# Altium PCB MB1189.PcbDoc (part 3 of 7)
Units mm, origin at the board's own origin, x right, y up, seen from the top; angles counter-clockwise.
Board outline 60.03 x 127.03 mm, 6 copper layers (TOP, L2_GND, L3_VCC, L4_SIG, L5_GND, BOTTOM), stack 1.58 mm thick; 273 components, 264 nets, 1114 pads, 811 vias.
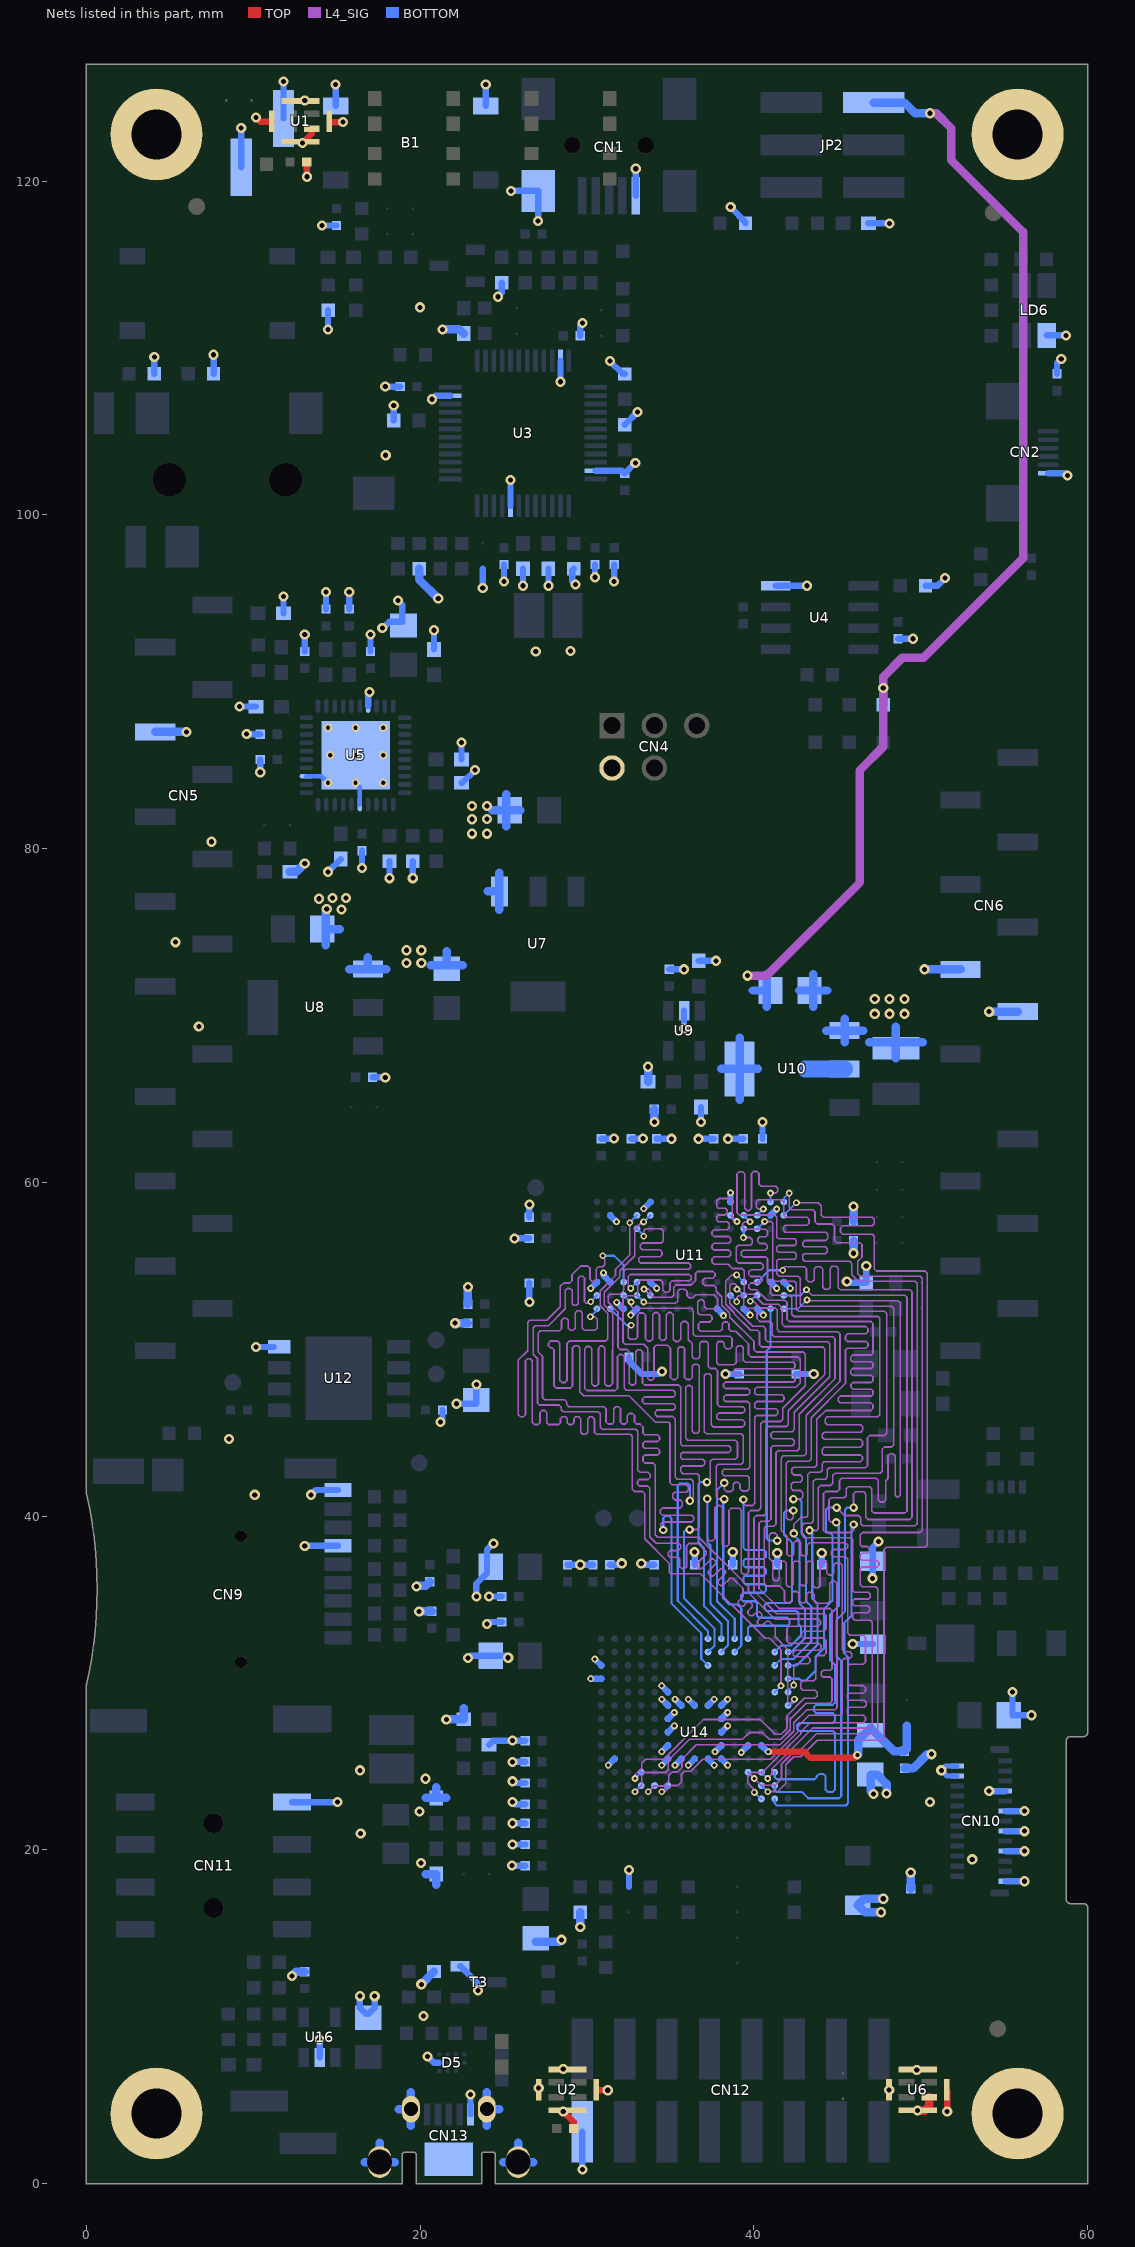
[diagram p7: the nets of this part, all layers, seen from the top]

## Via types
v1: diameter 0.61/0.61/0.61 (per signal layer), hole 0.305, TOP to BOTTOM, 321 vias
v2: diameter 0.508/0.508/0.508 (per signal layer), hole 0.254, TOP to BOTTOM, 247 vias
v3: diameter 0.406/0.406/0.406 (per signal layer), hole 0.203, TOP to BOTTOM, 243 vias

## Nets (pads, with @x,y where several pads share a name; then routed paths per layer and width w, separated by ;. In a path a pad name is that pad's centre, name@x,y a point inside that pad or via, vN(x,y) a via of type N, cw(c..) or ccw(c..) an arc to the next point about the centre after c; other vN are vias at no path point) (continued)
D5: U11.M8 U14.N9 | length 57
  L4_SIG w0.102: v3(32.561,57.578) 32.561,55.65 31.709,54.798 31.709,54.422 30.785,53.497 30.785,52.603 31.242,52.146 31.242,50.622 31.115,50.495 28.931,50.495 28.804,50.368 28.804,48.132 28.677,48.006 28.498,48.006 28.372,48.132 28.372,50.368 28.245,50.495 27.813,50.495 27.686,50.368 27.686,50.216 27.813,50.089 27.889,50.089 28.016,49.962 28.016,47.803 28.143,47.676 29.007,47.676 29.134,47.803 29.134,50.089 29.261,50.216 29.439,50.216 29.566,50.089 29.566,47.447 29.794,47.219 32.512,47.219 34.099,45.631 34.887,45.631 34.976,45.542 34.976,42.012 35.103,41.885 35.941,41.885 36.068,41.758 36.068,41.554 35.941,41.427 35.255,41.427 35.128,41.3 35.128,41.097 35.255,40.97 35.585,40.97 35.712,40.843 35.712,40.615 35.585,40.488 34.519,40.488 34.392,40.361 34.392,40.183 34.519,40.056 36.279,40.056 36.398,39.937 36.398,39.769 36.279,39.649 34.544,39.649 34.417,39.522 34.417,39.294 34.544,39.167 v2(34.569,39.167)
  BOTTOM w0.127: v3(32.561,57.578) 32.561,57.592 U11.M8@32.995,58.026 ; v2(34.569,39.167) 34.569,39.878 34.696,40.005 34.925,40.005 35.052,39.878 35.052,34.767 36.848,32.971 36.848,31.452 U14.N9@37.249,31.051
D6: U11.M7 U14.P9 | length 57.4
  L4_SIG w0.102: v3(33.401,56.769) 33.401,57.099 33.528,57.226 34.442,57.226 34.569,57.099 34.569,56.49 34.442,56.363 33.317,56.363 33.198,56.243 33.198,56.075 33.317,55.956 34.374,55.956 34.493,55.837 34.493,55.669 34.374,55.55 33.208,55.55 33.096,55.438 33.096,55.28 33.208,55.169 36.093,55.169 36.22,55.042 36.22,54.914 36.094,54.788 32.334,54.788 32.207,54.661 32.207,53.518 31.979,53.289 31.394,53.289 31.267,53.162 31.267,52.812 31.852,52.227 31.852,50.114 31.979,49.987 32.41,49.987 32.537,49.86 32.537,47.965 32.649,47.854 32.807,47.854 32.918,47.965 32.918,49.843 33.038,49.962 33.206,49.962 33.325,49.843 33.325,47.981 33.452,47.854 35.484,47.854 35.611,47.727 35.611,44.323 35.712,44.221 38.489,44.221 38.608,44.102 38.608,43.934 38.489,43.815 35.712,43.815 35.611,43.713 35.611,43.51 35.712,43.409 36.939,43.409 37.059,43.289 37.059,43.121 36.939,43.002 35.712,43.002 35.611,42.901 35.611,42.672 35.738,42.545 36.601,42.545 36.728,42.418 36.728,39.319 36.601,39.192 v2(36.144,39.192)
  BOTTOM w0.127: U11.M7@32.995,57.226 33.401,56.82 v3(33.401,56.769) ; v2(36.144,39.192) 35.941,39.192 35.814,39.065 35.814,35.083 37.647,33.25 37.647,32.249 U14.P9@37.249,31.851
D7: U11.L8 U14.R9 | length 56.9
  L4_SIG w0.102: v3(33.388,57.632) 33.299,57.632 32.855,57.188 32.855,55.613 31.953,54.712 31.953,54.331 31.039,53.416 31.039,52.654 31.547,52.146 31.547,49.987 31.521,49.962 31.521,47.93 31.394,47.803 31.191,47.803 31.064,47.93 31.064,50.063 30.937,50.19 30.81,50.19 30.683,50.063 30.683,47.922 30.564,47.803 30.396,47.803 30.277,47.922 30.277,50.046 30.158,50.165 29.99,50.165 29.87,50.046 29.87,47.65 29.997,47.523 31.699,47.523 31.826,47.65 31.826,49.563 31.945,49.682 32.113,49.682 32.233,49.563 32.233,47.676 32.36,47.549 35.161,47.549 35.281,47.43 35.281,47.262 35.161,47.142 33.444,47.142 33.325,47.023 33.325,46.855 33.444,46.736 35.169,46.736 35.281,46.624 35.281,46.467 35.169,46.355 34.198,46.355 34.087,46.243 34.087,46.086 34.198,45.974 35.128,45.974 35.281,45.822 35.281,42.342 35.408,42.215 36.246,42.215 36.373,42.088 36.373,41.046 36.246,40.919 v2(36.17,40.919)
  BOTTOM w0.127: v3(33.388,57.632) 33.401,57.645 33.414,57.645 U11.L8@33.795,58.026 ; v2(36.17,40.919) 36.17,41.834 36.043,41.961 35.56,41.961 35.433,41.834 35.433,34.925 37.249,33.109 U14.R9@37.249,32.651
D8: U11.L2 U14.P10 | length 56.8
  L4_SIG w0.102: v3(33.414,53.607) 33.692,53.607 33.807,53.492 33.807,53.238 33.934,53.111 35.077,53.111 35.204,53.238 35.204,53.721 35.331,53.848 36.246,53.848 36.5,54.102 36.5,54.559 36.601,54.661 37.549,54.661 37.668,54.542 37.668,54.374 37.549,54.254 37.059,54.254 36.932,54.127 36.932,53.95 37.059,53.823 37.617,53.823 37.744,53.696 37.744,53.467 38.075,53.137 38.075,52.629 38.557,52.146 38.557,51.918 40.005,50.47 40.005,49.962 40.132,49.835 42.951,49.835 43.078,49.708 43.078,47.803 41.732,46.457 41.732,45.796 41.605,45.669 40.538,45.669 40.411,45.542 40.411,40.462 40.284,40.335 39.802,40.335 39.675,40.208 39.675,36.626 39.548,36.5 39.369,36.5 39.243,36.626 39.243,40.335 39.116,40.462 38.633,40.462 38.506,40.335 38.506,38.321 38.387,38.202 38.219,38.202 38.1,38.321 38.1,40.514 37.974,40.64 37.795,40.64 37.668,40.514 37.668,38.659 37.541,38.532 37.338,38.532 37.211,38.659 v2(37.211,41.046)
  BOTTOM w0.127: v3(33.414,53.607) U11.L2@33.795,53.226 ; v2(37.211,41.046) 37.211,38.431 37.401,38.241 37.401,34.753 38.451,33.704 38.451,32.253 U14.P10@38.049,31.851
D9: U11.M3 U14.R10 | length 57.1
  L4_SIG w0.102: v3(32.618,53.649) 32.588,53.649 32.461,53.776 32.461,54.356 32.588,54.483 36.134,54.483 36.246,54.371 36.246,54.214 36.134,54.102 35.103,54.102 34.976,53.975 34.976,53.543 34.849,53.416 34.67,53.416 34.544,53.543 34.544,54.026 34.417,54.153 33.172,54.153 33.045,54.026 33.045,53.34 32.918,53.213 32.283,53.213 32.156,53.086 32.156,50.419 32.283,50.292 33.401,50.292 33.63,50.063 33.63,48.27 33.741,48.158 33.899,48.158 34.011,48.27 34.011,50.114 34.138,50.241 34.823,50.241 35.001,50.063 35.001,48.311 35.128,48.184 35.312,48.184 35.439,48.311 35.439,50.02 35.558,50.14 35.726,50.14 35.845,50.02 35.845,48.311 35.972,48.184 36.17,48.184 36.297,48.311 36.297,48.972 36.423,49.098 36.602,49.098 36.728,48.972 36.728,45.085 36.601,44.958 36.424,44.958 36.297,45.085 36.297,47.717 36.185,47.828 36.027,47.828 35.916,47.717 35.916,44.679 36.043,44.552 38.887,44.552 39.014,44.425 39.014,43.536 38.887,43.409 37.516,43.409 37.389,43.282 37.389,42.164 37.262,42.037 v2(37.186,42.037)
  BOTTOM w0.127: v3(32.618,53.649) U11.M3@32.995,54.026 ; v2(37.186,42.037) 36.813,42.037 36.686,41.91 36.686,38.417 37.02,38.083 37.02,34.595 38.049,33.567 U14.R10@38.049,32.651
D10: U11.M2 U14.R12 | length 57.9
  L4_SIG w0.102: v3(33.401,52.832) 33.477,52.756 35.306,52.756 35.433,52.883 35.433,53.467 35.56,53.594 35.865,53.594 35.992,53.467 35.992,53.213 36.119,53.086 36.347,53.086 36.525,53.264 37.592,53.264 37.821,53.035 37.821,52.553 37.694,52.426 37.16,52.426 37.033,52.553 37.033,52.84 36.914,52.959 36.746,52.959 36.627,52.84 36.627,52.197 36.754,52.07 37.364,52.07 37.49,51.944 37.49,51.765 37.364,51.638 36.805,51.638 36.678,51.511 36.678,51.206 36.805,51.079 37.973,51.079 38.1,51.206 38.1,51.511 38.227,51.638 38.379,51.638 38.506,51.511 38.506,51.206 38.633,51.079 38.913,51.079 39.675,50.317 39.675,49.682 39.827,49.53 42.647,49.53 42.774,49.403 42.774,47.981 42.52,47.727 40.183,47.727 40.056,47.6 40.056,47.371 40.157,47.269 41.689,47.269 41.808,47.15 41.808,46.982 41.689,46.863 40.157,46.863 40.056,46.761 40.056,46.533 40.157,46.431 41.326,46.431 41.427,46.33 41.427,46.126 41.326,46.025 40.157,46.025 40.056,45.923 40.056,40.767 39.929,40.64 39.497,40.64 39.37,40.767 v2(39.37,40.996)
  BOTTOM w0.127: U11.M2@32.995,53.226 33.389,52.832 v3(33.401,52.832) ; v2(39.37,40.996) 39.37,38.1 39.497,37.973 40.589,37.973 40.716,37.846 40.716,37.567 40.589,37.44 39.497,37.44 39.37,37.313 39.37,37.059 39.497,36.932 40.589,36.932 40.716,36.805 40.716,36.551 40.589,36.424 39.497,36.424 39.37,36.297 39.37,36.043 39.497,35.916 40.589,35.916 40.716,35.789 40.716,35.535 40.589,35.408 39.37,35.408 39.243,35.281 39.243,35.027 39.37,34.9 40.056,34.9 40.183,34.773 40.183,34.036 40.31,33.909 42.012,33.909 42.139,33.782 42.139,33.553 42.012,33.426 39.776,33.426 39.649,33.299 U14.R12@39.649,32.651
D11: U11.P1 U14.P11 | length 57.3
  L4_SIG w0.102: v3(32.639,51.435) 32.588,51.435 32.461,51.308 32.461,50.724 32.588,50.597 32.893,50.597 33.02,50.724 33.02,52.045 33.147,52.172 33.376,52.172 33.503,52.045 33.503,50.622 33.63,50.495 33.811,50.495 33.938,50.622 33.938,52.07 34.065,52.197 34.218,52.197 34.345,52.07 34.345,50.665 34.464,50.546 34.632,50.546 34.751,50.665 34.751,52.07 34.878,52.197 35.03,52.197 35.157,52.07 35.157,50.597 35.284,50.47 35.484,50.47 35.611,50.597 35.611,51.537 35.738,51.664 35.941,51.664 36.068,51.537 36.068,50.571 36.297,50.343 36.297,49.555 36.424,49.428 36.627,49.428 36.754,49.555 36.754,50.343 36.881,50.47 37.135,50.47 37.262,50.343 37.262,48.971 37.389,48.844 37.694,48.844 37.821,48.717 37.821,46.685 37.948,46.558 39.335,46.558 39.446,46.447 39.446,46.289 39.335,46.177 37.889,46.177 37.77,46.058 37.77,45.89 37.889,45.771 39.32,45.771 39.446,45.644 39.446,45.465 39.32,45.339 37.567,45.339 37.44,45.466 37.44,48.42 37.32,48.539 37.152,48.539 37.033,48.42 37.033,45.06 37.16,44.933 39.243,44.933 39.37,44.806 39.37,43.231 39.243,43.104 37.871,43.104 37.744,42.977 37.744,41.148 37.871,41.021 v2(38.227,41.021)
  BOTTOM w0.127: U11.P1@31.395,52.426 32.386,51.435 v3(32.639,51.435) ; v2(38.227,41.021) 38.163,40.957 38.163,35.069 38.536,34.696 39.014,34.696 39.243,34.468 39.243,32.245 39.146,32.148 U14.P11@38.849,31.851
D12: U11.N2 U14.R11 | length 56.8
  L4_SIG w0.102: v3(32.639,52.832) 32.639,52.578 32.766,52.451 36.246,52.451 36.373,52.324 36.373,50.902 36.5,50.775 38.557,50.775 38.684,50.648 38.684,50.165 38.557,50.038 38.354,50.038 38.227,50.165 38.227,50.343 38.1,50.47 37.897,50.47 37.77,50.343 37.77,49.2 37.897,49.073 38.811,49.073 38.938,49.2 38.938,50.089 39.065,50.216 39.244,50.216 39.37,50.089 39.37,49.352 39.497,49.225 42.351,49.225 42.469,49.108 42.469,48.941 42.351,48.824 38.899,48.824 38.786,48.711 38.786,48.551 38.899,48.438 42.35,48.438 42.469,48.319 42.469,48.151 42.35,48.031 38.288,48.031 38.176,47.92 38.176,47.762 38.288,47.65 39.636,47.65 39.751,47.535 39.751,47.372 39.636,47.257 38.317,47.257 38.202,47.141 38.202,46.978 38.317,46.863 39.624,46.863 39.751,46.736 39.751,42.926 39.624,42.799 38.212,42.799 38.1,42.687 38.1,42.53 38.212,42.418 39.599,42.418 39.726,42.292 39.726,41.631 39.599,41.504 39.294,41.504 39.167,41.631 39.167,41.91 39.04,42.037 38.887,42.037 38.76,41.91 38.76,41.605 38.633,41.478 38.354,41.478 38.227,41.605 v2(38.227,41.986)
  BOTTOM w0.127: U11.N2@32.195,53.226 32.589,52.832 v3(32.639,52.832) ; v2(38.227,41.986) 37.782,41.542 37.782,34.911 38.849,33.844 U14.R11@38.849,32.651
D13: U11.R1 U14.L15 | length 56.7
  L4_SIG w0.102: v3(30.201,51.943) 30.48,51.943 30.607,51.816 30.607,51.257 30.48,51.13 29.845,51.13 29.718,51.257 29.718,52.172 29.592,52.299 29.413,52.299 29.286,52.172 29.286,51.257 29.159,51.13 29.007,51.13 28.88,51.257 28.88,51.74 28.753,51.867 28.6,51.867 28.473,51.74 28.473,51.232 28.346,51.105 27.203,51.105 27.076,50.978 27.076,49.835 27.33,49.581 27.33,47.092 27.457,46.965 28.651,46.965 28.778,46.838 28.778,46.685 28.905,46.558 31.013,46.558 31.14,46.431 31.14,45.644 31.267,45.517 31.496,45.517 31.598,45.618 31.598,46.439 31.717,46.558 31.885,46.558 32.004,46.439 32.004,45.618 32.106,45.517 32.283,45.517 32.41,45.644 32.41,46.025 32.537,46.152 32.716,46.152 32.842,46.025 32.842,45.644 32.969,45.517 33.172,45.517 33.35,45.339 33.35,44.978 33.452,44.876 34.222,44.876 34.341,44.757 34.341,44.589 34.222,44.47 33.452,44.47 33.35,44.368 33.35,44.165 33.452,44.063 34.222,44.063 34.341,43.944 34.341,43.776 34.222,43.657 33.452,43.657 33.35,43.555 33.35,43.307 33.477,43.18 33.96,43.18 34.087,43.053 34.087,38.887 34.239,38.735 36.703,38.735 39.675,35.763 39.675,35.409 41.251,33.833 43.866,33.833 43.993,33.706 43.993,33.527 43.866,33.401 42.113,33.401 41.986,33.274 41.986,32.512 42.113,32.385 43.892,32.385 44.018,32.259 44.018,32.08 43.892,31.953 42.482,31.953 42.367,31.839 42.367,31.677 42.482,31.562 43.239,31.562 43.358,31.443 43.358,31.275 43.239,31.156 42.52,31.156 42.393,31.029 v3(42.393,29.871)
  BOTTOM w0.127: v3(30.201,51.943) 30.595,52.337 U11.R1@30.595,52.426 ; U14.L15@42.049,29.451 42.049,29.528 v3(42.393,29.871)
D14: U11.N3 U14.L14 | length 57.2
  L4_SIG w0.102: v3(30.94,55.601) 31.064,55.476 31.064,55.067 30.937,54.94 30.683,54.94 30.556,54.813 30.556,54.188 30.445,54.077 30.287,54.077 30.175,54.188 30.175,54.864 30.048,54.991 29.616,54.991 29.096,54.47 29.096,54.102 28.969,53.975 28.6,53.975 28.397,53.772 28.397,52.553 27.584,51.74 26.568,51.74 26.441,51.613 26.441,49.911 25.883,49.352 25.883,46.075 26.009,45.949 26.188,45.949 26.314,46.075 26.314,49.309 26.434,49.428 26.602,49.428 26.721,49.309 26.721,45.618 26.848,45.491 27.076,45.491 27.178,45.593 27.178,46.21 27.297,46.33 27.465,46.33 27.584,46.21 27.584,45.593 27.686,45.491 28.308,45.491 28.41,45.593 28.41,45.847 28.511,45.949 28.715,45.949 28.816,45.847 28.816,45.593 28.918,45.491 29.121,45.491 29.223,45.593 29.223,45.847 29.324,45.949 29.502,45.949 29.629,45.822 29.629,45.026 29.748,44.907 29.916,44.907 30.035,45.026 30.035,45.822 30.162,45.949 30.315,45.949 30.442,45.822 30.442,45.034 30.569,44.907 32.588,44.907 32.715,44.78 32.715,41.605 32.842,41.478 33.325,41.478 33.452,41.351 33.452,38.633 34.925,37.16 34.925,36.652 35.027,36.551 36.801,36.551 40.679,32.673 40.937,32.673 41.626,31.983 v3(41.626,29.828)
  BOTTOM w0.127: v3(30.94,55.601) 31.623,55.601 32.195,55.029 U11.N3@32.195,54.026 ; U14.L14@41.249,29.451 v3(41.626,29.828)
D15: U11.R2 U14.K15 | length 56.8
  L4_SIG w0.102: v3(30.218,52.849) 30.125,52.756 29.954,52.756 29.845,52.865 29.845,54.27 29.733,54.381 29.576,54.381 29.464,54.27 29.464,52.733 29.36,52.629 29.213,52.629 29.108,52.733 29.108,53.526 28.989,53.645 28.821,53.645 28.702,53.526 28.702,52.426 27.686,51.41 26.899,51.41 26.772,51.283 26.772,49.708 27.026,49.454 27.026,46.787 27.153,46.66 28.321,46.66 28.448,46.533 28.448,46.38 28.575,46.253 30.658,46.253 30.785,46.126 30.785,45.339 30.912,45.212 32.918,45.212 33.045,45.085 33.045,42.748 33.172,42.621 33.656,42.621 33.782,42.495 33.782,42.316 33.656,42.189 33.132,42.189 33.02,42.078 33.02,41.92 33.132,41.808 33.63,41.808 33.757,41.681 33.757,38.763 34.14,38.379 35.484,38.379 35.611,38.252 35.611,38.065 35.484,37.938 34.993,37.938 34.874,37.819 34.874,37.65 34.993,37.531 35.458,37.531 35.56,37.43 35.56,36.975 35.679,36.855 35.847,36.855 35.966,36.975 35.966,38.227 36.093,38.354 36.652,38.354 37.146,37.86 37.146,37.716 36.579,37.148 36.579,36.98 36.698,36.861 36.866,36.861 37.434,37.428 37.578,37.428 37.722,37.285 37.722,37.141 37.281,36.7 37.281,36.532 37.4,36.413 37.568,36.413 38.009,36.853 38.153,36.853 38.297,36.71 38.297,36.566 37.856,36.125 37.856,35.956 37.975,35.838 38.143,35.838 38.584,36.278 38.728,36.278 39.345,35.662 39.345,35.16 39.07,34.886 39.07,34.742 39.214,34.598 39.358,34.598 39.608,34.848 39.752,34.848 39.895,34.705 39.895,34.561 39.645,34.311 39.645,34.167 39.789,34.023 39.933,34.023 40.183,34.273 40.327,34.273 40.47,34.129 40.47,33.986 40.22,33.736 40.22,33.592 40.364,33.448 40.508,33.448 40.758,33.698 40.902,33.698 41.271,33.329 41.271,32.77 42.037,32.004 42.037,28.878 42.162,28.753 42.299,28.753 42.426,28.88 v3(42.426,29.028)
  BOTTOM w0.127: v3(30.218,52.849) U11.R2@30.595,53.226 ; U14.K15@42.049,28.651 v3(42.426,29.028)
D16: U11.E8 U14.P14 | length 57.3
  L4_SIG w0.102: v3(38.989,57.658) 38.837,57.658 38.71,57.785 38.71,58.903 38.583,59.03 37.897,59.03 37.77,58.903 37.77,58.559 37.871,58.458 38.286,58.458 38.405,58.339 38.405,58.171 38.286,58.051 37.871,58.051 37.77,57.95 37.77,57.747 37.871,57.645 38.413,57.645 38.532,57.526 38.532,57.289 38.405,57.162 37.61,57.162 37.49,57.043 37.49,56.875 37.61,56.756 38.489,56.756 38.608,56.637 38.608,56.469 38.489,56.35 37.61,56.35 37.49,56.231 37.49,56.062 37.61,55.943 38.489,55.943 38.608,55.824 38.608,55.656 38.489,55.537 37.617,55.537 37.49,55.41 37.49,55.22 37.617,55.093 38.456,55.093 38.71,54.839 39.294,54.839 39.421,54.712 39.421,53.416 39.548,53.289 39.98,53.289 40.564,52.705 41.478,52.705 41.707,52.476 41.707,51.486 41.834,51.359 46.711,51.359 46.838,51.232 46.838,51.053 46.711,50.927 45.618,50.927 45.491,50.8 45.491,50.571 45.593,50.47 46.718,50.47 46.838,50.351 46.838,50.183 46.718,50.063 45.593,50.063 45.491,49.962 45.491,47.955 43.434,45.898 43.434,43.409 43.307,43.282 42.062,43.282 41.935,43.155 41.935,39.903 42.062,39.776 42.241,39.776 42.367,39.903 v2(42.367,40.335)
  BOTTOM w0.127: U11.E8@38.595,58.026 38.621,58.026 v3(38.989,57.658) ; U14.P14@41.249,31.851 41.653,32.255 42.238,32.255 42.824,32.842 42.824,33.376 42.672,33.528 42.672,34.188 42.545,34.315 40.767,34.315 40.64,34.442 40.64,34.671 40.767,34.798 42.164,34.798 42.291,34.925 42.291,38.405 41.808,38.887 41.808,40.208 41.935,40.335 v2(42.367,40.335)
D17: U11.D7 U14.N14 | length 57.2
  L4_SIG w0.102: v3(39.37,56.693) 39.776,56.693 39.903,56.566 39.903,56.363 39.776,56.236 39.065,56.236 38.938,56.109 38.938,55.296 39.065,55.169 40.437,55.169 40.564,55.042 40.564,54.889 40.437,54.762 39.827,54.762 39.7,54.635 39.7,54.483 39.827,54.356 40.361,54.356 40.488,54.229 40.488,54.102 40.361,53.975 39.827,53.975 39.7,53.848 39.7,53.696 39.827,53.569 40.157,53.569 40.792,52.934 41.859,52.934 41.986,52.807 41.986,51.791 42.113,51.664 47.015,51.664 47.142,51.537 47.142,49.759 47.041,49.657 45.915,49.657 45.796,49.538 45.796,49.37 45.915,49.251 47.041,49.251 47.142,49.149 47.142,48.946 47.041,48.844 45.915,48.844 45.796,48.725 45.796,48.557 45.915,48.438 47.041,48.438 47.142,48.336 47.142,48.108 47.041,48.006 45.941,48.006 45.822,47.887 45.822,47.719 45.941,47.6 47.041,47.6 47.142,47.498 47.142,47.295 47.041,47.193 45.179,47.193 45.06,47.074 45.06,46.906 45.179,46.787 47.015,46.787 47.142,46.66 47.142,46.457 47.015,46.33 44.298,46.33 43.764,45.796 43.764,43.053 43.637,42.926 42.393,42.926 42.266,42.799 42.266,42.596 42.393,42.469 42.774,42.469 42.901,42.342 42.901,42.163 42.774,42.037 42.367,42.037 42.24,41.91 42.24,41.656 42.367,41.529 42.799,41.529 42.926,41.402 42.926,41.148 42.799,41.021 v2(42.367,41.021)
  BOTTOM w0.127: v3(39.37,56.693) 39.395,56.717 U11.D7@39.395,57.226 ; U14.N14@41.249,31.051 41.643,31.445 42.393,31.445 43.434,32.487 43.434,34.592 43.18,34.846 ; v2(42.367,41.021) 42.723,41.021 42.85,40.894 42.85,38.989 43.116,38.722 43.116,34.911 43.18,34.848
D18: U11.D8 U14.P15 | length 56.8
  L4_SIG w0.102: v3(39.766,57.643) 39.446,57.643 39.319,57.516 39.319,57.328 39.446,57.201 40.691,57.201 40.818,57.074 40.818,56.845 40.716,56.744 40.353,56.744 40.234,56.624 40.234,56.456 40.353,56.337 40.673,56.337 40.792,56.218 40.792,56.05 40.673,55.931 39.362,55.931 39.243,55.812 39.243,55.644 39.362,55.524 40.716,55.524 40.818,55.423 40.818,54.051 40.996,53.873 40.996,53.365 41.123,53.238 42.139,53.238 42.266,53.111 42.266,52.095 42.393,51.968 47.422,51.968 47.549,51.841 47.549,46.076 47.422,45.949 44.399,45.949 44.272,45.822 44.272,45.593 44.399,45.466 46.406,45.466 46.533,45.34 46.533,45.161 46.406,45.034 44.221,45.034 44.094,44.907 44.094,44.729 44.221,44.602 46.38,44.602 46.507,44.475 46.507,44.247 46.38,44.12 44.221,44.12 44.094,43.993 44.094,43.764 44.196,43.663 46.388,43.663 46.507,43.543 46.507,43.375 46.388,43.256 44.196,43.256 44.094,43.155 44.094,42.748 43.967,42.621 43.358,42.621 43.231,42.494 43.231,40.03 43.129,39.929 42.824,39.929 42.393,39.497 v2(42.393,38.964)
  BOTTOM w0.127: U11.D8@39.395,58.026 39.395,58.014 v3(39.766,57.643) ; U14.P15@42.049,31.851 42.24,31.851 43.053,32.664 43.053,34.434 42.799,34.688 ; v2(42.393,38.964) 42.393,38.862 42.735,38.519 42.735,34.753 42.799,34.69
D19: U11.B9 U14.N15 | length 57.2
  L4_SIG w0.102: v3(40.995,59.359) 41.3,59.359 41.427,59.486 41.427,59.639 41.3,59.766 40.437,59.766 40.31,59.893 40.31,60.528 40.183,60.655 39.98,60.655 39.853,60.528 39.853,58.445 39.726,58.318 39.573,58.318 39.446,58.445 39.446,60.503 39.319,60.63 39.116,60.63 38.989,60.503 38.989,58.175 39.116,58.048 41.25,58.048 41.377,57.921 41.377,56.723 41.478,56.621 42.443,56.621 42.545,56.519 42.545,56.316 42.443,56.215 41.478,56.215 41.377,56.113 41.377,55.91 41.478,55.808 42.443,55.808 42.545,55.707 42.545,55.503 42.443,55.402 41.478,55.402 41.377,55.3 41.377,54.534 41.529,54.381 42.647,54.381 42.774,54.254 42.774,52.705 42.901,52.578 48.26,52.578 48.387,52.451 48.387,44.272 48.26,44.145 47.828,44.145 47.701,44.018 47.701,42.697 47.574,42.57 44.856,42.57 44.729,42.443 44.729,41.961 44.602,41.834 43.993,41.834 43.866,41.707 43.866,39.243 43.764,39.141 v2(43.332,39.141)
  BOTTOM w0.127: U11.B9@40.995,58.826 v3(40.995,59.359) ; U14.N15@42.049,31.051 42.583,31.051 43.815,32.283 43.815,34.75 43.561,35.004 43.561,35.006 43.497,35.069 43.497,38.976 v2(43.332,39.141)
D20: U11.C8 U14.M15 | length 56.5
  L4_SIG w0.102: v3(40.572,58.403) 40.259,58.403 40.132,58.53 40.132,58.826 40.259,58.953 41.656,58.953 41.783,58.826 41.783,58.039 41.91,57.912 43.18,57.912 43.307,57.785 43.307,57.551 43.18,57.424 41.885,57.424 41.783,57.322 41.783,57.119 41.885,57.018 44.298,57.018 44.425,56.891 44.425,56.642 44.298,56.515 43.053,56.515 42.926,56.388 42.926,56.236 43.028,56.134 44.28,56.134 44.399,56.015 44.399,55.847 44.28,55.728 43.028,55.728 42.926,55.626 42.926,55.397 43.053,55.27 45.745,55.27 45.872,55.143 45.872,54.458 46.253,54.077 49.657,54.077 49.784,53.95 49.784,39.548 49.657,39.421 46.533,39.421 46.406,39.548 46.406,39.903 46.279,40.03 45.441,40.03 v2(44.958,40.513)
  BOTTOM w0.127: U11.C8@40.195,58.026 v3(40.572,58.403) ; U14.M15@42.049,30.251 42.723,30.251 42.824,30.15 43.104,30.15 43.688,30.734 43.688,31.561 44.196,32.069 44.196,34.417 44.704,34.925 44.704,38.862 44.577,38.989 44.45,38.989 44.323,39.116 44.323,40.386 44.45,40.513 v2(44.958,40.513)
D21: U11.A9 U14.E12 | length 57.8
  L4_SIG w0.102: v3(40.026,24.274) 40.424,23.876 41.275,23.876 41.656,24.257 41.656,25.121 41.707,25.171 41.707,25.18 42.477,25.95 42.74,25.95 43.748,26.958 47.202,26.958 47.422,27.178 47.422,35.636 47.295,35.763 46.507,35.763 46.38,35.89 46.38,36.852 46.482,36.954 47.379,36.954 47.498,37.073 47.498,37.241 47.379,37.36 46.482,37.36 46.38,37.462 46.38,37.665 46.482,37.767 46.812,37.767 46.914,37.868 46.914,38.072 46.812,38.173 46.482,38.173 46.38,38.275 46.38,38.887 46.507,39.014 49.962,39.014 50.089,39.141 50.089,54.254 49.962,54.381 46.38,54.381 46.228,54.534 46.228,55.27 46.482,55.524 46.482,56.261 46.355,56.388 44.958,56.388 44.831,56.515 44.831,57.379 44.704,57.506 43.79,57.506 43.663,57.633 43.663,58.242 43.536,58.369 42.24,58.369 42.113,58.496 v3(42.113,59.36)
  BOTTOM w0.127: U14.E12@39.649,24.651 v3(40.026,24.274) ; U11.A9@41.795,58.826 41.795,59.042 v3(42.113,59.36)
D22: U11.C7 U14.E13 | length 58
  L4_SIG w0.102: v3(40.64,57.658) 41.021,57.658 41.123,57.556 41.123,54.204 41.25,54.077 42.418,54.077 42.545,53.95 42.545,52.4 42.672,52.273 47.828,52.273 47.955,52.146 47.955,44.958 47.828,44.831 46.939,44.831 46.812,44.704 46.812,43.028 46.685,42.901 44.526,42.901 44.399,42.774 44.399,42.342 44.272,42.215 43.688,42.215 43.561,42.088 43.561,39.7 43.434,39.573 43.028,39.573 42.901,39.446 42.901,38.837 43.028,38.71 45.796,38.71 45.923,38.583 45.923,35.535 46.025,35.433 46.845,35.433 46.965,35.314 46.965,35.146 46.845,35.027 46.025,35.027 45.923,34.925 45.923,34.722 46.025,34.62 46.82,34.62 46.939,34.501 46.939,34.333 46.82,34.214 46.025,34.214 45.923,34.112 45.923,33.884 46.05,33.757 46.965,33.757 47.092,33.63 47.092,27.432 46.965,27.305 43.544,27.305 41.08,24.841 41.08,24.528 v3(40.826,24.274)
  BOTTOM w0.127: U11.C7@40.195,57.226 40.208,57.226 v3(40.64,57.658) ; U14.E13@40.449,24.651 v3(40.826,24.274)
D23: U11.A8 U14.D13 | length 56.3
  L4_SIG w0.102: v3(40.826,23.474) 40.847,23.495 41.427,23.495 41.91,23.978 41.91,25.095 42.393,25.578 42.799,25.578 43.79,26.568 47.676,26.568 47.803,26.695 47.803,37.998 47.93,38.125 50.267,38.125 50.394,38.252 50.394,54.559 50.267,54.686 47.346,54.686 47.219,54.813 47.219,56.769 47.092,56.896 45.314,56.896 45.187,57.023 45.187,57.277 45.314,57.404 47.092,57.404 47.219,57.531 47.219,57.785 47.092,57.912 44.171,57.912 44.044,58.039 44.044,58.598 43.866,58.776 v3(42.545,58.776)
  BOTTOM w0.127: U14.D13@40.449,23.851 v3(40.826,23.474) ; U11.A8@41.795,58.026 v3(42.545,58.776)
D24: U11.A2 U14.E14 | length 56.9
  L4_SIG w0.102: v3(43.155,53.569) 43.485,53.238 49.047,53.238 49.174,53.111 49.174,40.31 49.047,40.183 47.193,40.183 47.066,40.31 47.066,41.631 46.939,41.758 45.669,41.758 45.542,41.631 45.542,41.224 45.415,41.097 44.628,41.097 44.501,40.97 44.501,39.751 44.628,39.624 v2(44.933,39.624)
  BOTTOM w0.127: U14.E14@41.249,24.651 41.249,24.359 41.376,24.232 43.637,24.232 43.764,24.359 43.764,24.409 43.891,24.536 44.171,24.536 44.298,24.409 44.298,23.597 44.425,23.47 44.729,23.47 44.856,23.597 44.856,27 44.729,27.127 42.723,27.127 42.596,27.254 42.596,27.483 42.723,27.61 44.729,27.61 44.856,27.737 44.856,28.059 44.729,28.186 43.739,28.186 43.612,28.313 43.612,28.567 43.739,28.694 44.729,28.694 44.856,28.821 44.856,31.084 44.577,31.363 44.577,34.112 45.085,34.62 45.085,39.497 44.958,39.624 v2(44.933,39.624) ; U11.A2@41.795,53.226 42.812,53.226 v3(43.155,53.569)
D25: U11.C3 U14.D14 | length 56.9
  L4_SIG w0.102: v3(41.732,54.737) 41.732,54.813 41.859,54.94 43.028,54.94 43.155,54.813 43.155,54.178 43.282,54.051 43.49,54.051 43.609,54.17 43.609,54.813 43.736,54.94 43.993,54.94 44.12,54.813 44.12,53.721 44.247,53.594 44.45,53.594 44.577,53.721 44.577,54.839 44.704,54.966 44.933,54.966 45.06,54.839 45.06,53.696 45.187,53.569 49.352,53.569 49.479,53.442 49.479,39.929 49.352,39.802 46.838,39.802 46.711,39.929 46.711,41.326 46.584,41.453 46.101,41.453 45.974,41.326 v2(45.974,40.513)
  BOTTOM w0.127: U11.C3@40.195,54.026 40.906,54.737 v3(41.732,54.737) ; U14.D14@41.249,23.851 41.249,23.571 41.363,23.457 42.888,23.457 43.256,23.089 45.11,23.089 45.237,23.216 45.237,31.318 44.958,31.598 44.958,33.782 45.466,34.29 45.466,40.386 45.593,40.513 v2(45.974,40.513)
D26: U11.A1 U14.C14 | length 56.8
  L4_SIG w0.102: v3(43.18,52.959) 43.231,52.908 48.641,52.908 48.768,52.781 48.768,41.25 48.641,41.123 48.59,41.123 48.463,41.25 48.463,43.612 48.336,43.739 48.158,43.739 48.031,43.612 48.031,42.24 47.904,42.113 47.904,40.97 47.777,40.843 47.574,40.843 47.447,40.97 47.447,42.139 47.32,42.266 45.263,42.266 45.136,42.139 45.136,41.605 45.009,41.478 44.298,41.478 44.171,41.351 44.171,39.141 44.298,39.014 45.847,39.014 45.974,39.141 v2(45.974,39.497)
  BOTTOM w0.102: U11.A1@41.795,52.426 42.647,52.426 v3@43.155,52.934
  BOTTOM w0.127: U14.C14@41.249,23.051 41.249,22.784 41.376,22.657 45.517,22.657 45.644,22.784 45.644,31.547 45.415,31.775 45.415,33.604 45.847,34.036 45.847,39.37 v2(45.974,39.497) ; v3@43.155,52.934 v3(43.18,52.959)
D27: U11.C2 U14.C13 | length 57.9
  L4_SIG w0.102: v3(39.787,52.882) 39.98,52.882 40.386,52.476 41.275,52.476 41.402,52.349 41.402,51.181 41.529,51.054 45.034,51.054 45.161,50.927 45.161,48.082 43.129,46.05 43.129,43.739 43.002,43.612 41.758,43.612 41.631,43.485 41.631,39.141 41.986,38.786 41.986,37.719 42.088,37.617 42.291,37.617 42.393,37.719 42.393,38.387 42.512,38.506 42.68,38.506 42.799,38.387 42.799,37.719 42.901,37.617 43.104,37.617 43.205,37.719 43.205,38.278 43.332,38.405 45.491,38.405 45.618,38.278 45.618,38.125 45.491,37.998 44.78,37.998 44.653,37.872 44.653,37.693 44.78,37.567 45.491,37.567 45.618,37.44 45.618,32.995 45.745,32.868 46.558,32.868 46.685,32.741 46.685,31.242 46.558,31.115 45.745,31.115 45.618,30.988 45.618,29.972 45.745,29.845 46.558,29.845 46.685,29.718 46.685,29.515 46.558,29.388 45.72,29.388 45.593,29.261 45.593,29.083 45.72,28.956 46.617,28.956 46.736,28.837 46.736,28.669 46.617,28.55 45.72,28.55 45.593,28.423 45.593,28.194 45.72,28.067 46.558,28.067 46.685,27.94 46.685,27.737 46.558,27.61 43.358,27.61 42.824,27.076 42.824,26.949 40.513,24.638 39.878,24.638 39.624,24.384 39.624,24.006 40.03,23.599 v3(40.03,23.442)
  BOTTOM w0.127: v3(39.787,52.882) 40.13,53.226 U11.C2@40.195,53.226 ; v3(40.03,23.442) 40.421,23.051 U14.C13@40.449,23.051
D28: U11.B1 U14.D6 | length 56.6
  L4_SIG w0.102: v3(34.472,23.474) 34.65,23.474 35.027,23.851 35.433,23.851 35.662,24.079 35.662,24.536 35.839,24.714 36.22,24.714 36.936,25.429 40.993,25.429 42.621,27.058 42.621,27.381 43.307,28.067 45.161,28.067 45.288,28.194 45.288,31.344 45.415,31.471 45.753,31.471 45.872,31.59 45.872,31.758 45.753,31.877 45.415,31.877 45.288,32.004 45.288,37.059 45.161,37.186 44.907,37.186 44.78,37.059 44.78,36.594 44.661,36.474 44.492,36.474 44.373,36.594 44.373,37.186 44.272,37.287 44.068,37.287 43.967,37.186 43.967,35.832 43.848,35.712 43.68,35.712 43.56,35.832 43.56,37.186 43.459,37.287 43.256,37.287 43.154,37.186 43.154,35.959 43.035,35.839 42.867,35.839 42.748,35.959 42.748,37.186 42.646,37.287 42.443,37.287 42.341,37.186 42.341,35.882 42.222,35.763 42.054,35.763 41.935,35.882 41.935,37.186 41.833,37.287 41.63,37.287 41.528,37.186 41.528,36.238 41.409,36.119 41.241,36.119 41.122,36.238 41.122,37.262 40.919,37.465 40.919,38.862 41.046,38.989 41.275,38.989 41.402,38.862 v2(41.402,38.532)
  BOTTOM w0.127: v3(34.472,23.474) U14.D6@34.849,23.851 ; U11.B1@40.995,52.426 40.995,50.139 40.767,49.911 40.767,38.659 40.894,38.532 v2(41.402,38.532)
D29: U11.D2 U14.D4 | length 57
  L4_SIG w0.102: v3(32.872,23.474) 33.274,23.876 33.274,24.511 33.401,24.638 34.722,24.638 34.874,24.79 34.874,25.349 36.144,26.619 39.319,26.619 39.726,27.026 40.513,27.026 40.919,26.619 41.608,26.619 42.185,27.197 42.185,27.834 43.129,28.778 44.552,28.778 44.679,28.905 44.679,30.25 44.577,30.352 44.163,30.352 44.044,30.471 44.044,30.639 44.163,30.758 44.577,30.758 44.679,30.86 44.679,34.341 44.552,34.468 41.504,34.468 40.31,35.662 40.31,39.573 40.437,39.7 40.894,39.7 41.021,39.827 41.021,44.094 41.148,44.221 42.299,44.221 42.418,44.341 42.418,44.509 42.299,44.628 41.148,44.628 41.021,44.755 41.021,44.933 41.148,45.06 42.291,45.06 42.418,45.187 42.418,46.228 44.552,48.362 44.552,50.317 44.425,50.444 40.818,50.444 40.691,50.571 40.691,51.257 40.564,51.384 39.929,51.384 38.557,52.756 38.557,53.797 38.684,53.924 38.862,53.924 38.989,53.797 v3(38.989,53.594)
  BOTTOM w0.127: v3(32.872,23.474) U14.D4@33.249,23.851 ; v3(38.989,53.594) 39.027,53.594 U11.D2@39.395,53.226
D30: U11.D3 U14.E4 | length 56.9
  L4_SIG w0.102: v3(32.872,24.274) 32.872,24.49 33.274,24.892 33.274,25.179 33.524,25.429 34.599,25.429 36.982,27.813 40.386,27.813 41.275,26.924 41.625,26.924 41.982,27.281 41.982,28.037 43.028,29.083 43.663,29.083 43.79,29.21 43.79,29.439 43.663,29.566 42.926,29.566 42.799,29.693 42.799,29.997 42.926,30.124 43.586,30.124 43.713,30.251 43.713,31.521 43.84,31.648 44.196,31.648 44.323,31.775 44.323,32.563 44.196,32.69 42.977,32.69 42.85,32.817 42.85,32.969 42.977,33.096 44.196,33.096 44.323,33.223 44.323,34.049 44.221,34.151 41.364,34.151 40.005,35.51 40.005,39.903 40.132,40.03 40.589,40.03 40.716,40.157 40.716,45.237 40.843,45.364 41.935,45.364 42.062,45.491 42.062,46.304 44.247,48.489 44.247,50.013 44.12,50.14 40.462,50.14 40.335,50.267 40.335,51.003 40.208,51.13 39.802,51.13 38.824,52.108 38.824,52.184 38.316,52.692 38.316,54.089 38.684,54.458 v3(38.964,54.458)
  BOTTOM w0.127: v3(32.872,24.274) U14.E4@33.249,24.651 ; v3(38.964,54.458) U11.D3@39.395,54.026
D31: U11.E2 U14.D5 | length 56.7
  L4_SIG w0.102: v3(33.672,23.474) 34.027,23.83 34.625,23.83 34.9,24.105 34.9,24.46 35.103,24.663 35.408,24.663 35.687,24.943 35.687,25.425 36.551,26.289 41.565,26.289 42.388,27.112 42.388,27.605 43.18,28.397 44.856,28.397 44.983,28.524 44.983,35.967 44.857,36.093 44.678,36.093 44.552,35.967 44.552,34.9 44.425,34.773 43.739,34.773 43.612,34.9 43.612,35.306 43.485,35.433 43.282,35.433 43.155,35.306 43.155,34.925 43.028,34.798 42.824,34.798 42.697,34.925 42.697,35.357 42.57,35.484 42.393,35.484 42.266,35.357 42.266,34.925 42.139,34.798 41.961,34.798 41.834,34.925 41.834,35.535 41.554,35.814 40.767,35.814 40.615,35.966 40.615,39.268 40.742,39.395 41.199,39.395 41.326,39.522 41.326,43.79 41.453,43.917 42.596,43.917 42.723,44.044 42.723,46.101 44.856,48.235 44.856,50.622 44.729,50.749 41.224,50.749 41.097,50.876 41.097,51.537 40.97,51.664 40.361,51.664 40.183,51.841 40.183,52.248 39.98,52.451 39.522,52.451 39.395,52.578 39.395,53.086 39.268,53.213 39.099,53.213 38.972,53.086 v3(38.972,52.849)
  BOTTOM w0.127: v3(33.672,23.474) U14.D5@34.049,23.851 ; U11.E2@38.595,53.226 v3(38.972,52.849)
DSI_VDD12: C86.1 C87.2 SB14.1 U14.G13 | length 12.3
  TOP w0.381: v3(40.869,25.874) 43.036,25.874 43.383,25.527 46.05,25.527 v2(46.203,25.679)
  BOTTOM w0.381: U14.G13@40.449,26.251 40.826,25.874 v3(40.869,25.874)
  BOTTOM w0.508: v2(46.203,25.679) 46.253,25.73 46.253,26.568 46.99,27.305 48.387,25.908 C87.2@49.022,25.908 49.149,26.035 SB14.1@49.149,27.432
E5V: C35.1 D2.1 JP2.1 U10.2 U10.4 | length 78.2
  L4_SIG w0.508: v1(39.624,72.39) 40.767,72.39 46.355,77.978 46.355,84.709 47.752,86.106 v1(47.752,89.637) 47.752,90.297 48.895,91.44 50.165,91.44 56.134,97.409 56.134,116.967 51.816,121.285 51.816,123.19 50.927,124.079 v1(50.546,124.079)
  BOTTOM w0.508: 38.035,66.802 U10.4@39.141,66.802 ; 39.141,64.947 U10.4@39.141,66.802 ; 39.141,68.657 U10.4@39.141,66.802 ; 39.928,71.501 C35.1@40.767,71.501 ; 40.246,66.802 U10.4@39.141,66.802 ; 40.767,70.535 C35.1@40.767,71.501 ; 40.767,72.467 C35.1@40.767,71.501 ; JP2.1@47.179,124.714 49.022,124.714 49.657,124.079 v1(50.546,124.079) ; D2.1@47.752,88.628 v1(47.752,89.637)
  BOTTOM w1.016: 43.078,66.802 U10.2@45.441,66.802
GND: B1.2 B1.3 C1.1 C2.1 C3.1 C5.1 C6.1 C7.1 C8.1 C9.1 C10.2 C11.2 C12.1 C13.1 C14.1 C15.2 C16.2 C17.2 C19.1 C22.1 C23.1 C24.1 C25.2 C26.2 C27.1 C29.2 C30.2 C31.2 C32.2 C33.1 C34.1 C35.2 C36.2 C37.2 C38.2 C39.1 C40.1 C41.2 C42.2 C43.2 C44.2 C45.2 C46.2 C47.2 C48.2 C49.2 C50.2 C51.2 C52.2 C53.2 C54.2 C57.2 C58.2 C59.2 C60.2 C62.2 C65.2 C67.2 C68.2 C69.2 C70.2 C71.2 C72.2 C73.2 C74.2 C75.2 C76.2 C77.1 C78.1 C80.2 C81.2 C82.2 C83.2 C84.2 C85.2 C86.2 C87.1 C88.2 C89.2 C90.2 C91.2 C92.2 C93.2 C94.2 C95.2 C96.2 C97.1 C98.2 C101.2 CN1.5 CN1.6 CN2.6 CN4.2 CN5.7 CN6.6 CN6.7 CN9.6 CN9.9 CN10.2 CN10.4 CN10.7 CN10.11 CN10.15 CN10.19 CN10.25 CN11.7 CN12.2 CN13.5 CN13.6 CN13.7 CN13.8 CN13.9 CN13.10 D5.D2 H1.1 H2.1 H3.1 H4.1 JP1.1 JP1.2 L2.1 LD5.2 LD6.1 LD7.2 R8.2 R16.1 R19.2 R23.2 R24.2 R25.2 R26.1 R27.1 R28.1 R29.1 R32.1 R37.2 R39.2 R40.2 R47.2 R48.1 R122.1 R144.2 R152.1 R154.1 SB4.1 SB15.1 T3.2 U1.2 U1.5 U2.5 U3.8 U3.23 U3.35 U3.47 U4.4 U5.3 U5.17 U5.35 U5.41 U6.2 U6.5 U7.1 U8.1 U9.2 U10.1 U11.A3 U11.B3 U11.B8 U11.C1 U11.D1 U11.E9 U11.F1 U11.L3 U11.L9 U11.M1 U11.N1 U11.P3 U11.P8 U11.R3 U12.4 U14.F2 U14.F6 U14.F7 U14.F8 U14.F9 U14.F10 U14.G6 U14.G10 U14.G12 U14.H6 U14.H10 U14.J6 U14.J10 U14.K6 U14.K7 U14.K8 U14.K9 U14.K10 U14.L6 U14.M1 U14.N1 U16.2 | length 244.9
  TOP w0.381: v1(10.16,123.825) 10.414,123.571 U1.5@11.074,123.571 ; v1(12.954,122.301) 13.502,122.849 U1.2@13.502,123.146 ; v1(13.208,120.269) C1.1@13.208,121.158 ; U1.5@14.58,123.546 v1(15.367,123.546) ; v1(28.575,4.318) 29.21,3.683 C2.1@29.21,3.302 ; U2.5@30.607,5.588 v1(31.242,5.588) ; v1(51.584,4.318) U6.5@51.584,5.563
  TOP w0.508: v1(49.809,4.369) 50.241,4.369 50.506,4.633 U6.2@50.506,5.163
  BOTTOM w0.279: U5.3@13.179,84.348 14.077,84.348 v2(14.478,83.947) ; v2(16.129,83.947) 16.379,83.697 U5.35@16.379,82.648
  BOTTOM w0.305: CN10.4@52.175,24.417 51.58,24.417 v1(51.232,24.765) 51.484,25.017 CN10.2@52.175,25.017
  BOTTOM w0.381: R24.2@4.064,108.458 v1(4.064,109.474) ; R23.2@7.62,108.458 v1(7.62,109.601) ; v1(9.169,88.519) C22.1@10.16,88.519 ; JP1.1@9.271,120.841 v1(9.271,123.19) ; v1(9.601,86.868) C23.1@10.414,86.868 ; v1(10.16,50.139) U12.4@11.213,50.139 ; v1(10.414,84.582) C25.2@10.414,85.344 ; C13.1@11.811,94.107 v1(11.811,95.123) ; JP1.2@11.811,123.761 v1(11.811,125.984) ; CN11.7@12.318,22.86 v1(15.037,22.86) ; v1(13.081,38.217) CN9.6@15.071,38.217 ; C17.2@13.081,91.821 v1(13.081,92.837) ; v1(13.462,41.275) 13.754,41.567 CN9.9@15.071,41.567 ; U16.2@13.97,7.563 v1(13.97,8.636) ; v1(14.122,117.348) C3.1@14.986,117.348 ; R40.2@14.351,94.361 v1(14.351,95.377) ; v1(14.478,78.613) C31.2@15.24,79.375 ; v1(14.478,111.125) R19.2@14.478,112.268 ; B1.3@14.931,124.523 v1(14.931,125.802) ; R39.2@15.748,94.361 v1(15.748,95.377) ; v1(16.383,11.227) 16.383,10.541 16.764,10.16 16.891,10.16 17.272,10.541 v1(17.272,11.227) ; v1(16.51,78.842) C30.2@16.51,79.883 ; U5.17@16.879,88.548 16.879,89.298 v1(16.969,89.388) ; C16.2@17.018,91.821 v1(17.018,92.837) ; C41.2@17.145,66.294 v1(17.907,66.294) ; v1(17.729,93.218) 17.78,93.218 18.161,93.599 18.923,93.599 18.923,94.615 v1(18.669,94.869) ; v1(17.907,107.696) C7.1@18.796,107.696 ; v1(18.161,78.232) R48.1@18.161,79.248 ; R26.1@18.415,105.664 v1(18.415,106.553) ; v1(19.558,78.232) R47.2@19.558,79.248 ; v1(20.447,7.62) 20.828,7.239 D5.D2@21.145,7.239 ; v1(20.701,106.934) 20.919,107.152 U3.23@21.812,107.152 ; C19.1@20.828,91.948 v1(20.828,93.091) ; v1(21.209,45.644) 21.336,45.771 C62.2@21.336,46.355 ; v1(22.174,46.736) 23.368,46.736 v1(23.368,47.879) ; T3.2@22.395,13.015 22.418,13.015 23.47,11.963 v1(23.47,11.57) ; C27.1@22.479,83.947 22.528,83.947 v1(23.29,84.709) ; C24.1@22.479,85.344 v1(22.479,86.36) ; v1(22.86,31.496) 22.987,31.623 24.003,31.623 25.159,31.623 v1(25.273,31.509) ; CN13.5@23.017,4.135 v1(23.017,5.334) ; v1(23.368,35.179) 23.368,35.941 24.003,36.576 24.003,36.957 24.003,37.973 v1(24.384,38.354) ; v1(23.749,95.631) SB4.1@23.749,96.774 ; B1.2@23.931,124.523 v1(23.931,125.802) ; v1(24.003,33.528) 24.13,33.655 C78.1@24.892,33.655 ; C85.2@24.13,26.289 24.384,26.543 v1(25.531,26.543) C84.2@26.289,26.543 ; v1(24.13,35.179) C77.1@24.892,35.179 ; v1(24.663,113.081) 24.892,113.309 R16.1@24.892,113.919 ; v1(25.019,96.012) C12.1@25.019,97.028 ; U3.8@25.412,100.552 v1(25.412,102.096) ; v1(25.446,119.426) CN1.6@27.068,119.426 v1(27.068,117.619) ; v1(25.502,19.054) C95.2@26.289,19.054 ; v1(25.527,22.86) 25.654,22.733 C90.2@26.289,22.733 ; v1(25.527,24.105) 25.552,24.105 25.654,24.003 C89.2@26.289,24.003 ; v1(25.527,25.26) 25.54,25.273 C88.2@26.289,25.273 ; v1(25.531,20.32) C92.2@26.289,20.32 ; v1(25.531,21.59) C91.2@26.289,21.59 ; v1(25.654,56.642) C50.2@26.543,56.642 ; v1(26.162,95.758) C11.2@26.162,96.774 ; v1(26.543,52.832) C52.2@26.543,53.975 ; C48.2@26.543,57.912 v1(26.543,58.674) ; v1(27.686,95.758) C10.2@27.686,96.774 ; v1(28.412,107.986) U3.35@28.412,109.252 ; C74.2@28.829,37.084 v1(29.591,37.084) C73.2@30.353,37.084 ; R29.1@29.21,96.774 29.108,96.672 29.108,96.037 v1(29.312,95.834) ; C5.1@29.591,110.744 29.591,111.379 v1(29.718,111.506) ; v1(29.718,0.84) CN12.2@29.718,3.113 ; v3(30.218,53.649) U11.R3@30.595,54.026 ; v3(30.226,30.251) U14.M1@30.849,30.251 ; v3(30.472,31.428) U14.N1@30.849,31.051 ; v1(30.48,96.266) R28.1@30.48,97.028 ; U3.47@30.512,102.652 32.095,102.652 C8.1@32.258,102.489 v1(32.893,103.124) ; C47.2@30.861,62.611 31.598,62.611 v1(31.623,62.636) ; v3(30.988,54.574) 30.988,54.433 U11.P3@31.395,54.026 ; v3(31.272,25.074) U14.F2@31.649,25.451 ; C72.2@31.369,37.084 31.993,37.084 v1(32.08,37.171) ; v1(31.369,109.22) 32.131,108.458 R25.2@32.258,108.458 ; U11.P8@31.395,58.026 31.395,58.012 v3(31.765,57.641) ; v1(31.623,96.012) C9.1@31.623,97.028 ; v3(31.776,52.806) 32.156,52.426 U11.N1@32.195,52.426 ; R27.1@32.258,105.41 v1(33.02,106.172) ; SB15.1@32.512,17.78 v1(32.512,18.796) ; C59.2@32.512,49.53 32.512,49.276 33.274,48.514 34.29,48.514 34.442,48.666 v1(34.493,48.666) ; v3(32.618,52.049) U11.M1@32.995,52.426 ; C46.2@32.639,62.611 33.325,62.611 v1(33.35,62.636) ; CN1.5@32.918,119.126 v1(32.918,120.752) ; v1(33.249,37.156) 33.32,37.084 C71.2@34.036,37.084 ; v3(33.401,58.42) 33.696,58.715 33.696,58.727 U11.L9@33.795,58.826 ; U11.L3@33.795,54.026 v3(34.172,53.649) ; C45.2@34.163,62.611 v1(35.052,62.611) ; v3(34.472,25.074) U14.F6@34.849,25.451 ; v3(34.472,25.874) U14.G6@34.849,26.251 ; v3(34.472,29.028) U14.K6@34.849,28.651 ; v3(34.472,29.828) U14.L6@34.849,29.451 ; U14.H6@34.849,27.051 35.226,27.428 v3(35.234,27.428) ; U14.J6@34.849,27.851 35.226,28.228 v3(35.234,28.228) ; C34.1@34.925,72.771 v1(35.814,72.771) ; v3(35.272,25.074) U14.F7@35.649,25.451 ; v3(35.272,29.028) U14.K7@35.649,28.651 ; v1(35.814,69.215) U9.2@35.814,70.288 ; v3(36.072,25.074) U14.F8@36.449,25.451 ; v3(36.072,29.028) U14.K8@36.449,28.651 ; C70.2@36.449,37.084 v1(36.449,37.846) ; v1(36.678,62.611) C44.2@37.592,62.611 ; C33.1@36.703,73.279 v1(37.719,73.279) ; v1(36.83,63.627) C39.1@36.83,64.516 ; U14.F9@37.249,25.451 v3(37.626,25.074) ; U14.K9@37.249,28.651 v3(37.626,29.028) ; v3(37.672,25.874) U14.G10@38.049,26.251 ; U11.F1@37.795,52.426 38.176,52.045 v3(38.176,52.019) ; U14.F10@38.049,25.451 v3(38.426,25.074) ; U14.H10@38.049,27.051 v3(38.426,27.428) ; U14.J10@38.049,27.851 v3(38.426,28.228) ; U14.K10@38.049,28.651 v3(38.426,29.028) ; v1(38.303,48.514) C58.2@39.116,48.514 ; v1(38.456,62.611) C43.2@39.37,62.611 ; U11.E9@38.595,58.826 v3(38.595,59.385) ; v1(38.608,118.453) 38.608,118.44 39.497,117.551 R8.2@39.497,117.475 ; C69.2@38.735,37.084 v1(38.735,37.846) ; v3(39.243,25.832) 39.243,25.845 U14.G12@39.649,26.251 ; U11.D1@39.395,52.426 v3(39.772,52.049) ; U11.C1@40.195,52.426 v3(40.572,52.049) ; C42.2@40.513,62.611 v1(40.513,63.627) ; U11.B3@40.995,54.026 v3(41.372,53.649) ; U11.B8@40.995,58.026 v3(41.372,58.403) ; U4.4@41.318,95.758 v1(43.18,95.758) ; C68.2@41.402,37.084 v1(41.402,37.795) ; U11.A3@41.795,54.026 v3(42.172,53.649) ; C57.2@42.545,48.514 v1(43.586,48.514) ; C67.2@44.069,37.084 v1(44.069,37.795) ; v1(45.568,54.051) 45.644,53.975 L2.1@46.736,53.975 v1(46.736,54.991) ; v1(45.923,32.334) C81.2@47.117,32.334 ; LD5.2@46.863,117.475 v1(48.133,117.475) ; v1(47.117,36.271) C76.2@47.117,37.287 47.117,38.125 v1(47.473,38.481) ; C14.1@48.641,92.583 v1(49.53,92.583) ; R37.2@50.292,95.758 51.003,95.758 v1(51.46,96.215) ; v1(54.102,23.517) CN10.7@55.075,23.517 ; CN10.25@55.075,18.117 v1(56.226,18.117) ; CN10.19@55.075,19.917 v1(56.226,19.917) ; CN10.15@55.075,21.117 v1(56.226,21.117) ; CN10.11@55.075,22.317 v1(56.226,22.317) ; v1(55.499,29.464) 55.499,28.067 v1(56.642,28.067) ; LD6.1@57.555,110.767 v1(58.699,110.767) ; CN2.6@57.635,102.509 58.654,102.509 v1(58.801,102.362) ; C6.1@58.166,108.458 58.166,109.093 v1(58.42,109.347)
  BOTTOM w0.508: CN5.7@4.127,86.995 v1(5.994,86.995) ; LD7.2@12.192,78.613 12.573,78.613 v1(13.081,79.121) ; v1(12.319,12.446) 12.573,12.7 R152.1@13.081,12.7 ; 14.351,74.218 C32.2@14.351,75.184 ; v1@14.351,76.15 C32.2@14.351,75.184 ; 15.19,75.184 C32.2@14.351,75.184 ; 15.761,72.785 U8.1@16.866,72.785 ; 16.665,1.28 CN13.9@17.567,1.28 ; 16.866,73.497 U8.1@16.866,72.785 ; 17.567,2.436 CN13.9@17.567,1.28 ; 17.972,72.785 U8.1@16.866,72.785 ; 18.469,1.28 CN13.9@17.567,1.28 ; 18.705,4.46 CN13.6@19.442,4.46 ; 19.442,3.456 CN13.6@19.442,4.46 ; 19.442,5.464 CN13.6@19.442,4.46 ; v1(19.788,35.79) 19.812,35.79 19.836,35.814 20.32,35.814 C75.2@20.574,36.068 ; v1(19.939,34.29) R122.1@20.701,34.29 ; R32.1@19.939,96.774 19.939,96.139 v1(21.082,94.996) ; v1(20.066,11.938) R154.1@20.828,12.7 ; 20.345,18.542 C93.2@20.955,18.542 20.955,17.894 ; 20.345,23.114 C94.2@20.955,23.114 ; 20.624,73.025 C37.2@21.59,73.025 ; 20.955,23.762 C94.2@20.955,23.114 ; v1(21.336,111.125) 22.352,111.125 C26.2@22.606,110.871 ; v1(21.565,27.813) C83.2@22.606,27.813 22.606,28.499 ; 21.565,23.114 C94.2@20.955,23.114 ; 21.59,73.864 C37.2@21.59,73.025 ; v1(22.098,51.562) C54.2@22.86,51.562 ; 22.556,73.025 C37.2@21.59,73.025 ; C53.2@22.86,52.705 v1(22.86,53.721) ; 23.992,3.456 CN13.7@23.992,4.46 ; 23.992,5.464 CN13.7@23.992,4.46 ; 24.039,77.445 U7.1@24.751,77.445 ; 24.307,82.296 C29.2@25.146,82.296 ; 24.729,4.46 CN13.7@23.992,4.46 ; 24.751,76.34 U7.1@24.751,77.445 ; 24.751,78.551 U7.1@24.751,77.445 ; 24.965,1.28 CN13.8@25.867,1.28 ; 25.146,81.33 C29.2@25.146,82.296 ; 25.146,83.262 C29.2@25.146,82.296 ; 25.867,2.436 CN13.8@25.867,1.28 ; C29.2@25.985,82.296 C29.2@25.146,82.296 ; 26.769,1.28 CN13.8@25.867,1.28 ; C98.2@26.924,14.478 28.334,14.478 v1(28.461,14.605) ; v1(29.591,15.367) R144.2@29.591,16.256 ; C38.2@33.655,66.04 v1(33.655,66.929) ; v1(34.036,63.627) C40.1@34.036,64.389 ; C35.2@42.722,71.501 C35.2@43.561,71.501 ; 43.561,70.535 C35.2@43.561,71.501 ; 43.561,72.467 C35.2@43.561,71.501 ; 44.336,69.102 U10.1@45.441,69.102 ; 44.4,71.501 C35.2@43.561,71.501 ; 45.441,68.39 U10.1@45.441,69.102 ; 45.441,69.814 U10.1@45.441,69.102 ; v1(45.974,55.753) C51.2@45.974,56.515 ; C49.2@45.974,57.658 v1(45.974,58.547) ; 46.547,69.102 U10.1@45.441,69.102 ; 46.913,68.389 C36.2@48.514,68.389 ; v1(47.168,23.343) 46.99,23.52 46.99,24.511 47.396,24.511 47.955,23.952 v1(47.955,23.368) ; v1(47.625,16.256) 46.66,16.256 C96.2@46.228,16.688 46.609,17.069 v1(47.752,17.069) ; C36.2@48.514,67.436 C36.2@48.514,68.389 ; 48.514,69.343 C36.2@48.514,68.389 ; C87.1@49.022,24.892 49.555,24.892 50.394,25.73 v1(50.648,25.73) ; C97.1@49.403,17.653 v1(49.403,18.644) ; 50.115,68.389 C36.2@48.514,68.389 ; v1(50.215,72.771) CN6.6@52.387,72.771 ; v1(54.102,70.231) CN6.7@55.816,70.231
  other v1: 48.108,5.613 27.102,5.715 49.759,6.807 28.575,6.858 20.193,10.033 20.041,19.202 53.086,19.431 16.434,20.98 19.964,22.301 50.546,22.86 20.32,24.257 16.383,24.765 10.084,41.275 8.534,44.628 6.731,69.342 47.244,70.104 48.133,70.104 49.022,70.104 47.244,70.993 48.133,70.993 49.022,70.993 19.177,73.152 20.066,73.152 19.177,73.914 20.066,73.914 5.334,74.397 15.291,76.352 14.402,76.378 13.939,77 14.735,77.035 15.561,77.038 7.493,80.416 23.114,80.899 24.003,80.899 23.109,81.765 24.003,81.788 23.114,82.55 24.003,82.55 26.924,91.821 29.007,91.846 17.932,103.581 19.99,112.446 13.081,124.841
  other v2: 17.78,83.947 14.605,85.598 16.129,85.598 17.78,85.598 14.478,87.249 16.129,87.249 17.78,87.249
